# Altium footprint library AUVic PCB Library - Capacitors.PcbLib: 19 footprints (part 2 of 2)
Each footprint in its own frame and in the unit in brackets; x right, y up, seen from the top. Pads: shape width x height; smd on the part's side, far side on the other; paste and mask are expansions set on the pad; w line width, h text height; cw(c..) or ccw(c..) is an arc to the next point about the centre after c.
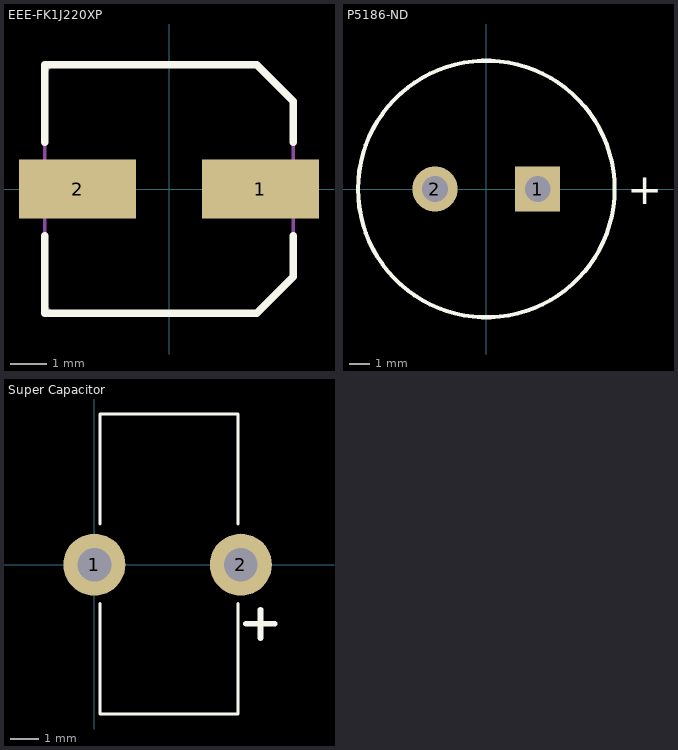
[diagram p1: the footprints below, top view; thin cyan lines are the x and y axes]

## EEE-FK1J220XP [mm] "Capacitor, SMD, Digi#PCE3821CT-ND, Panasonic-ECG"
height 7.7
pads (2):
  rect 3.2x1.6 smd: 1(2.5,0) 2(-2.5,0)
Top Overlay:
  lines w0.2: -3.4,-1.27 -3.4,-3.4 2.4,-3.4 3.4,-2.4 3.4,-1.27 ; -3.4,1.27 -3.4,3.4 2.4,3.4 3.4,2.4 3.4,1.27
Mechanical 13:
  lines w0.1: -3.4,-3.05 ccw(c-3.05,-3.05) -3.05,-3.4 2.4,-3.4 3.4,-2.4 3.4,2.4 2.4,3.4 -3.05,3.4 ccw(c-3.05,3.05) -3.4,3.05 -3.4,-3.05
3D body: height 0.5, standoff 0, extent -3.407,-3.407 3.401,3.407
3D body: height 7.7, standoff 0.05, extent -3.373,-3.393 3.4,3.393

## P5186-ND [mm] "Capacitor, THT, Digi#732-1209-1-ND, Panasonic-ECG"
height 25
pads (2):
  rect 2.2x2.2 hole 1.25: 1(2.5,0)
  round 2.2 hole 1.25: 2(-2.5,0)
Top Overlay:
  circle w0.2: c0,0 r6.25
  text "+" at 6.862,-0.737 h1.5
3D body: height 0, standoff -4, extent 2.153,-0.349 2.85,0.349
3D body: height 25, standoff 0, extent -6.201,-6.238 6.25,6.238
3D body: height 0, standoff -4, extent -2.847,-0.349 -2.15,0.349

## Super Capacitor [mm]
pads (2):
  round 2.2 hole 1.2: 1(0,0) 2(5.2,0)
Top Overlay:
  lines w0.1: 0.2,-1.375 0.2,-5.3 5.1,-5.3 5.1,-1.375 ; 0.2,1.45 0.2,5.35 5.1,5.35 5.1,1.45
  lines w0.2: 5.384,-2.1 6.4,-2.1 ; 5.9,-2.6 5.9,-1.6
